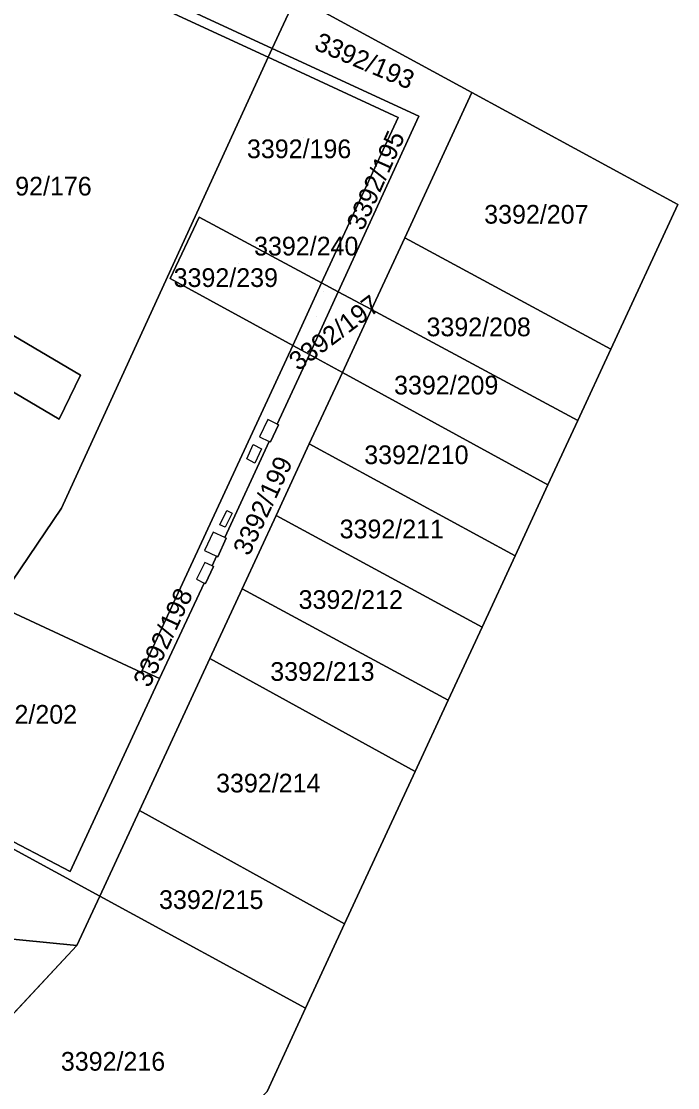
# Model space of a CAD drawing. Extents: x -262715 to -259381, y -1237238 to -1231182.
# Drawn here: x -261371.9 to -261301.7, y -1236043.8 to -1235929.8 of the extents above; entities that cross this region are included whole.
import ezdxf

# ---------------------------------------------------------------- set-up
doc = ezdxf.new("R2010")
doc.units = 0
for name, color, linetype in [('body_kn', 7, 'Continuous'), ('kladpar_druhypozemkov', 7, 'Continuous'), ('kladpar_hranice', 7, 'Continuous'), ('kladpar_parcelnecisla', 7, 'Continuous'), ('kladpar_plochy', 7, 'Continuous'), ('kladpar_sipky', 7, 'Continuous'), ('zappar_hrandruhpozemk', 7, 'Continuous'), ('zuob_linie', 7, 'Continuous'), ('zuob_plochy', 7, 'Continuous')]:
    doc.layers.add(name, color=color, linetype=linetype)

msp = doc.modelspace()

# ---------------------------------------------------------------- linework, layer by layer
at = {"layer": 'body_kn'}
for p, q in [((-261345.49, -1235933.67), (-261345.49, -1235933.67)), ((-261345.49, -1235933.67), (-261345.49, -1235933.67)), ((-261345.06, -1235932.74), (-261345.06, -1235932.74)), ((-261323.71, -1235937.45), (-261323.71, -1235937.45)), ((-261323.71, -1235937.45), (-261323.71, -1235937.45)), ((-261331.59, -1235940.11), (-261331.59, -1235940.11)), ((-261331.59, -1235940.11), (-261331.59, -1235940.11)), ((-261329.38, -1235939.99), (-261329.38, -1235939.99)), ((-261301.71, -1235949.44), (-261301.71, -1235949.44)), ((-261352.89, -1235950.78), (-261352.89, -1235950.78)), ((-261330.9, -1235952.98), (-261330.9, -1235952.98)), ((-261330.9, -1235952.98), (-261330.9, -1235952.98)), ((-261355.98, -1235957.32), (-261355.98, -1235957.32)), ((-261339.79, -1235957.8), (-261339.79, -1235957.8)), ((-261339.79, -1235957.8), (-261339.79, -1235957.8)), ((-261338.02, -1235958.75), (-261338.02, -1235958.75)), ((-261334.46, -1235960.66), (-261334.46, -1235960.66)), ((-261334.46, -1235960.66), (-261334.46, -1235960.66)), ((-261342.88, -1235964.48), (-261342.88, -1235964.48)), ((-261342.88, -1235964.48), (-261342.88, -1235964.48)), ((-261341.1, -1235965.45), (-261341.1, -1235965.45)), ((-261308.86, -1235964.89), (-261308.86, -1235964.89)), ((-261308.86, -1235964.89), (-261308.86, -1235964.89)), ((-261365.58, -1235967.67), (-261365.58, -1235967.67)), ((-261365.58, -1235967.67), (-261365.58, -1235967.67)), ((-261337.57, -1235967.38), (-261337.57, -1235967.38)), ((-261337.57, -1235967.38), (-261337.57, -1235967.38)), ((-261367.87, -1235972.36), (-261367.87, -1235972.36)), ((-261345.53, -1235972.42), (-261345.53, -1235972.42)), ((-261312.39, -1235972.5), (-261312.39, -1235972.5)), ((-261312.39, -1235972.5), (-261312.39, -1235972.5)), ((-261344.54, -1235972.92), (-261344.54, -1235972.92)), ((-261344.54, -1235972.92), (-261344.54, -1235972.92)), ((-261344.4, -1235972.99), (-261344.4, -1235972.99)), ((-261346.42, -1235974.27), (-261346.42, -1235974.27)), ((-261345.38, -1235974.75), (-261345.38, -1235974.75)), ((-261345.24, -1235974.81), (-261345.24, -1235974.81)), ((-261347.09, -1235975.08), (-261347.09, -1235975.08)), ((-261346.22, -1235975.54), (-261346.22, -1235975.54)), ((-261346.22, -1235975.54), (-261346.22, -1235975.54)), ((-261341.11, -1235975.02), (-261341.11, -1235975.02)), ((-261341.11, -1235975.02), (-261341.11, -1235975.02)), ((-261347.79, -1235976.62), (-261347.79, -1235976.62)), ((-261346.92, -1235977.06), (-261346.92, -1235977.06)), ((-261315.58, -1235979.39), (-261315.58, -1235979.39)), ((-261315.58, -1235979.39), (-261315.58, -1235979.39)), ((-261367.6, -1235981.9), (-261367.6, -1235981.9)), ((-261349.93, -1235982.14), (-261349.93, -1235982.14)), ((-261349.37, -1235982.41), (-261349.37, -1235982.41)), ((-261349.37, -1235982.41), (-261349.37, -1235982.41)), ((-261344.65, -1235982.66), (-261344.65, -1235982.66)), ((-261344.65, -1235982.66), (-261344.65, -1235982.66)), ((-261350.66, -1235983.66), (-261350.66, -1235983.66)), ((-261350.1, -1235983.93), (-261350.1, -1235983.93)), ((-261351.39, -1235984.44), (-261351.39, -1235984.44)), ((-261350.12, -1235985.03), (-261350.12, -1235985.03)), ((-261350.12, -1235985.03), (-261350.12, -1235985.03)), ((-261350, -1235985.09), (-261350, -1235985.09)), ((-261352.32, -1235986.4), (-261352.32, -1235986.4)), ((-261351.04, -1235987.03), (-261351.04, -1235987.03)), ((-261350.9, -1235987.1), (-261350.9, -1235987.1)), ((-261319.1, -1235986.99), (-261319.1, -1235986.99)), ((-261319.1, -1235986.99), (-261319.1, -1235986.99)), ((-261352.27, -1235987.68), (-261352.27, -1235987.68)), ((-261351.5, -1235988.04), (-261351.5, -1235988.04)), ((-261351.5, -1235988.04), (-261351.5, -1235988.04)), ((-261351.35, -1235988.11), (-261351.35, -1235988.11)), ((-261353.17, -1235989.48), (-261353.17, -1235989.48)), ((-261352.35, -1235989.89), (-261352.35, -1235989.89)), ((-261352.21, -1235989.96), (-261352.21, -1235989.96)), ((-261348.29, -1235990.52), (-261348.29, -1235990.52)), ((-261348.29, -1235990.52), (-261348.29, -1235990.52)), ((-261322.63, -1235994.6), (-261322.63, -1235994.6)), ((-261322.63, -1235994.6), (-261322.63, -1235994.6)), ((-261351.74, -1235997.96), (-261351.74, -1235997.96)), ((-261351.74, -1235997.96), (-261351.74, -1235997.96)), ((-261359.06, -1235999.44), (-261359.06, -1235999.44)), ((-261359.06, -1235999.44), (-261359.06, -1235999.44)), ((-261358.98, -1235999.25), (-261358.98, -1235999.25)), ((-261358.98, -1235999.25), (-261358.98, -1235999.25)), ((-261357.12, -1236000.09), (-261357.12, -1236000.09)), ((-261326.26, -1236002.43), (-261326.26, -1236002.43)), ((-261326.26, -1236002.43), (-261326.26, -1236002.43)), ((-261329.78, -1236010.04), (-261329.78, -1236010.04)), ((-261329.78, -1236010.04), (-261329.78, -1236010.04)), ((-261359.26, -1236014.2), (-261359.26, -1236014.2)), ((-261359.26, -1236014.2), (-261359.26, -1236014.2)), ((-261366.66, -1236020.74), (-261366.66, -1236020.74)), ((-261363.51, -1236023.37), (-261363.51, -1236023.37)), ((-261363.51, -1236023.37), (-261363.51, -1236023.37)), ((-261337.33, -1236026.34), (-261337.33, -1236026.34)), ((-261337.33, -1236026.34), (-261337.33, -1236026.34)), ((-261365.96, -1236028.66), (-261365.96, -1236028.66)), ((-261365.96, -1236028.66), (-261365.96, -1236028.66)), ((-261341.5, -1236035.34), (-261341.5, -1236035.34)), ((-261341.5, -1236035.34), (-261341.5, -1236035.34))]:
    msp.add_line(p, q, dxfattribs=at)
at = {"layer": 'kladpar_druhypozemkov'}
for p, q in [((-261333.62, -1235933.87), (-261333.62, -1235933.87)), ((-261341.71, -1235942.24), (-261341.71, -1235942.24)), ((-261331.15, -1235942.12), (-261331.15, -1235942.12)), ((-261369.71, -1235946.22), (-261369.71, -1235946.22)), ((-261315.71, -1235949.59), (-261315.71, -1235949.59)), ((-261348.71, -1235955.73), (-261348.71, -1235955.73)), ((-261322.04, -1235961.03), (-261322.04, -1235961.03)), ((-261340.38, -1235961.45), (-261340.38, -1235961.45)), ((-261337.55, -1235961.63), (-261337.55, -1235961.63)), ((-261326.52, -1235968.14), (-261326.52, -1235968.14)), ((-261329.49, -1235975.4), (-261329.49, -1235975.4)), ((-261346.4, -1235980.79), (-261346.4, -1235980.79)), ((-261332.46, -1235983.48), (-261332.46, -1235983.48)), ((-261353.75, -1235990.87), (-261353.75, -1235990.87)), ((-261336.31, -1235991.07), (-261336.31, -1235991.07)), ((-261339.57, -1235998.82), (-261339.57, -1235998.82)), ((-261369.87, -1236003.1), (-261369.87, -1236003.1)), ((-261344.78, -1236010.35), (-261344.78, -1236010.35)), ((-261351.16, -1236022.87), (-261351.16, -1236022.87)), ((-261361.38, -1236039.96), (-261361.38, -1236039.96))]:
    msp.add_line(p, q, dxfattribs=at)
at = {"layer": 'kladpar_hranice'}
for p, q in [((-261330.9, -1235952.98), (-261323.71, -1235937.45)), ((-261339.79, -1235957.8), (-261331.59, -1235940.11)), ((-261342.88, -1235964.48), (-261339.79, -1235957.8)), ((-261339.79, -1235957.8), (-261342.88, -1235964.48)), ((-261338.02, -1235958.75), (-261341.1, -1235965.45)), ((-261341.1, -1235965.45), (-261338.02, -1235958.75)), ((-261339.79, -1235957.8), (-261338.02, -1235958.75)), ((-261338.02, -1235958.75), (-261339.79, -1235957.8)), ((-261338.02, -1235958.75), (-261334.46, -1235960.66)), ((-261358.98, -1235999.25), (-261342.88, -1235964.48)), ((-261341.1, -1235965.45), (-261342.88, -1235964.48)), ((-261342.88, -1235964.48), (-261341.1, -1235965.45)), ((-261383.94, -1236047.9), (-261365.96, -1236028.66))]:
    msp.add_line(p, q, dxfattribs=at)
for points in [[(-261386.5, -1236069.65), (-261377.1, -1236074.79), (-261372.8, -1236072.22), (-261361.27, -1236060.35), (-261345.62, -1236044.25), (-261341.5, -1236035.34), (-261337.33, -1236026.34), (-261329.78, -1236010.04), (-261326.26, -1236002.43), (-261322.63, -1235994.6), (-261319.1, -1235986.99), (-261315.58, -1235979.39), (-261312.39, -1235972.5), (-261308.86, -1235964.89), (-261301.71, -1235949.44), (-261323.71, -1235937.45), (-261341.89, -1235927.54), (-261342.66, -1235927.5), (-261305.98, -1235847.48)], [(-261342.66, -1235927.5), (-261345.06, -1235932.74), (-261371.51, -1235920.48), (-261371.49, -1235920.03), (-261371.41, -1235919.44), (-261371.21, -1235918.88), (-261369.08, -1235914.38), (-261379.31, -1235909.59)], [(-261345.49, -1235933.67), (-261370.16, -1235922.25), (-261370.19, -1235922.32), (-261370.81, -1235921.97), (-261371.03, -1235921.8), (-261371.22, -1235921.56), (-261371.45, -1235921.01), (-261371.51, -1235920.48), (-261345.06, -1235932.74), (-261345.49, -1235933.67)], [(-261385.72, -1235955.84), (-261372.29, -1235926.85), (-261370.19, -1235922.32), (-261370.16, -1235922.25), (-261345.49, -1235933.67), (-261367.6, -1235981.9), (-261374.62, -1235992.24), (-261397.64, -1235981.58), (-261397.56, -1235981.41), (-261396.6, -1235979.34), (-261394.51, -1235974.82)], [(-261338.02, -1235958.75), (-261329.38, -1235939.99), (-261345.06, -1235932.74), (-261342.66, -1235927.5)], [(-261341.89, -1235927.54), (-261323.71, -1235937.45), (-261330.9, -1235952.98), (-261334.46, -1235960.66), (-261338.02, -1235958.75)], [(-261342.88, -1235964.48), (-261358.98, -1235999.25), (-261359.06, -1235999.44), (-261374.62, -1235992.24), (-261367.6, -1235981.9), (-261345.49, -1235933.67)], [(-261331.59, -1235940.11), (-261345.49, -1235933.67), (-261345.06, -1235932.74), (-261329.38, -1235939.99), (-261338.02, -1235958.75)], [(-261345.49, -1235933.67), (-261331.59, -1235940.11), (-261339.79, -1235957.8)], [(-261323.71, -1235937.45), (-261301.71, -1235949.44), (-261308.86, -1235964.89), (-261330.9, -1235952.98)], [(-261342.88, -1235964.48), (-261355.98, -1235957.32), (-261352.89, -1235950.78), (-261339.79, -1235957.8)], [(-261339.79, -1235957.8), (-261352.89, -1235950.78), (-261355.98, -1235957.32), (-261342.88, -1235964.48)], [(-261334.46, -1235960.66), (-261330.9, -1235952.98), (-261308.86, -1235964.89)], [(-261365.58, -1235967.67), (-261381.27, -1235958.45), (-261385.72, -1235955.84)], [(-261385.72, -1235955.84), (-261381.27, -1235958.45), (-261365.58, -1235967.67)], [(-261387.89, -1235960.55), (-261384.17, -1235962.74), (-261367.87, -1235972.36), (-261365.58, -1235967.67)], [(-261365.58, -1235967.67), (-261367.87, -1235972.36), (-261384.17, -1235962.74), (-261387.89, -1235960.55)], [(-261334.46, -1235960.66), (-261337.57, -1235967.38), (-261341.1, -1235965.45)], [(-261337.57, -1235967.38), (-261334.46, -1235960.66), (-261312.39, -1235972.5)], [(-261308.86, -1235964.89), (-261312.39, -1235972.5), (-261334.46, -1235960.66)], [(-261390.31, -1236026.25), (-261389.52, -1236024.31), (-261383.32, -1236012.04), (-261366.66, -1236020.74), (-261357.12, -1236000.09), (-261352.35, -1235989.89), (-261352.21, -1235989.96), (-261351.35, -1235988.11), (-261351.5, -1235988.04), (-261351.04, -1235987.03), (-261350.9, -1235987.1), (-261350, -1235985.09), (-261350.12, -1235985.03), (-261345.38, -1235974.75), (-261345.24, -1235974.81), (-261344.4, -1235972.99), (-261344.54, -1235972.92), (-261341.1, -1235965.45)], [(-261341.1, -1235965.45), (-261337.57, -1235967.38), (-261341.11, -1235975.02), (-261344.65, -1235982.66), (-261348.29, -1235990.52), (-261351.74, -1235997.96), (-261359.26, -1236014.2), (-261363.51, -1236023.37), (-261383.03, -1236012.76)], [(-261341.1, -1235965.45), (-261344.54, -1235972.92), (-261344.4, -1235972.99), (-261345.24, -1235974.81), (-261345.38, -1235974.75), (-261350.12, -1235985.03), (-261350, -1235985.09), (-261350.9, -1235987.1), (-261351.04, -1235987.03), (-261351.5, -1235988.04), (-261351.35, -1235988.11), (-261352.21, -1235989.96), (-261352.35, -1235989.89), (-261357.12, -1236000.09), (-261358.98, -1235999.25)], [(-261341.11, -1235975.02), (-261337.57, -1235967.38), (-261315.58, -1235979.39)], [(-261312.39, -1235972.5), (-261315.58, -1235979.39), (-261337.57, -1235967.38)], [(-261344.65, -1235982.66), (-261341.11, -1235975.02), (-261319.1, -1235986.99)], [(-261315.58, -1235979.39), (-261319.1, -1235986.99), (-261341.11, -1235975.02)], [(-261348.29, -1235990.52), (-261344.65, -1235982.66), (-261322.63, -1235994.6)], [(-261319.1, -1235986.99), (-261322.63, -1235994.6), (-261344.65, -1235982.66)], [(-261351.74, -1235997.96), (-261348.29, -1235990.52), (-261326.26, -1236002.43)], [(-261322.63, -1235994.6), (-261326.26, -1236002.43), (-261348.29, -1235990.52)], [(-261359.06, -1235999.44), (-261358.98, -1235999.25), (-261357.12, -1236000.09), (-261366.66, -1236020.74), (-261383.32, -1236012.04), (-261389.52, -1236024.31), (-261379.2, -1235999), (-261374.62, -1235992.24), (-261359.06, -1235999.44)], [(-261359.26, -1236014.2), (-261351.74, -1235997.96), (-261329.78, -1236010.04)], [(-261326.26, -1236002.43), (-261329.78, -1236010.04), (-261351.74, -1235997.96)], [(-261329.78, -1236010.04), (-261337.33, -1236026.34), (-261359.26, -1236014.2)], [(-261383.03, -1236012.76), (-261363.51, -1236023.37), (-261365.96, -1236028.66), (-261389.8, -1236026.3)], [(-261363.51, -1236023.37), (-261359.26, -1236014.2), (-261337.33, -1236026.34)], [(-261365.96, -1236028.66), (-261363.51, -1236023.37), (-261341.5, -1236035.34)], [(-261337.33, -1236026.34), (-261341.5, -1236035.34), (-261363.51, -1236023.37)], [(-261390.31, -1236026.25), (-261389.8, -1236026.3), (-261365.96, -1236028.66), (-261383.94, -1236047.9)], [(-261341.5, -1236035.34), (-261345.62, -1236044.25), (-261361.27, -1236060.35), (-261377.4, -1236051.49)]]:
    msp.add_lwpolyline(points, dxfattribs=at)
at = {"layer": 'kladpar_plochy'}
for points in [[(-261345.62, -1236044.25), (-261341.5, -1236035.34), (-261337.33, -1236026.34), (-261329.78, -1236010.04), (-261326.26, -1236002.43), (-261322.63, -1235994.6), (-261319.1, -1235986.99), (-261315.58, -1235979.39), (-261312.39, -1235972.5), (-261308.86, -1235964.89), (-261301.71, -1235949.44), (-261323.71, -1235937.45), (-261341.89, -1235927.54), (-261342.66, -1235927.5), (-261305.98, -1235847.48)], [(-261383.32, -1236012.04), (-261366.66, -1236020.74), (-261357.12, -1236000.09), (-261352.35, -1235989.89), (-261352.21, -1235989.96), (-261351.35, -1235988.11), (-261351.5, -1235988.04), (-261351.04, -1235987.03), (-261350.9, -1235987.1), (-261350, -1235985.09), (-261350.12, -1235985.03), (-261345.38, -1235974.75), (-261345.24, -1235974.81), (-261344.4, -1235972.99), (-261344.54, -1235972.92), (-261341.1, -1235965.45), (-261337.57, -1235967.38), (-261341.11, -1235975.02), (-261344.65, -1235982.66), (-261348.29, -1235990.52), (-261351.74, -1235997.96), (-261359.26, -1236014.2), (-261363.51, -1236023.37), (-261383.03, -1236012.76)]]:
    msp.add_lwpolyline(points, dxfattribs=at)
for points in [[(-261356.13, -1235921.41), (-261346.13, -1235927.3), (-261342.66, -1235927.5), (-261345.06, -1235932.74), (-261371.51, -1235920.48), (-261371.49, -1235920.03), (-261371.41, -1235919.44), (-261371.21, -1235918.88), (-261369.08, -1235914.38), (-261379.31, -1235909.59), (-261378.64, -1235908.15)], [(-261345.49, -1235933.67), (-261370.16, -1235922.25), (-261370.19, -1235922.32), (-261370.81, -1235921.97), (-261371.03, -1235921.8), (-261371.22, -1235921.56), (-261371.45, -1235921.01), (-261371.51, -1235920.48), (-261345.06, -1235932.74)], [(-261365.58, -1235967.67), (-261381.27, -1235958.45), (-261385.72, -1235955.84), (-261372.29, -1235926.85), (-261370.19, -1235922.32), (-261370.16, -1235922.25), (-261345.49, -1235933.67), (-261367.6, -1235981.9), (-261374.62, -1235992.24), (-261397.64, -1235981.58), (-261397.56, -1235981.41), (-261396.6, -1235979.34), (-261394.51, -1235974.82), (-261392.97, -1235975.72), (-261374.7, -1235986.37), (-261373.56, -1235984.04), (-261391.5, -1235973.55), (-261393.4, -1235972.44), (-261387.89, -1235960.55), (-261384.17, -1235962.74), (-261367.87, -1235972.36)], [(-261341.89, -1235927.54), (-261323.71, -1235937.45), (-261330.9, -1235952.98), (-261334.46, -1235960.66), (-261338.02, -1235958.75), (-261329.38, -1235939.99), (-261345.06, -1235932.74), (-261342.66, -1235927.5)], [(-261345.49, -1235933.67), (-261331.59, -1235940.11), (-261339.79, -1235957.8), (-261352.89, -1235950.78), (-261355.98, -1235957.32), (-261342.88, -1235964.48), (-261358.98, -1235999.25), (-261359.06, -1235999.44), (-261374.62, -1235992.24), (-261367.6, -1235981.9)], [(-261331.59, -1235940.11), (-261345.49, -1235933.67), (-261345.06, -1235932.74), (-261329.38, -1235939.99), (-261338.02, -1235958.75), (-261339.79, -1235957.8)], [(-261323.71, -1235937.45), (-261301.71, -1235949.44), (-261308.86, -1235964.89), (-261330.9, -1235952.98)], [(-261339.79, -1235957.8), (-261342.88, -1235964.48), (-261355.98, -1235957.32), (-261352.89, -1235950.78)], [(-261334.46, -1235960.66), (-261330.9, -1235952.98), (-261308.86, -1235964.89), (-261312.39, -1235972.5)], [(-261365.58, -1235967.67), (-261367.87, -1235972.36), (-261384.17, -1235962.74), (-261387.89, -1235960.55), (-261385.72, -1235955.84), (-261381.27, -1235958.45)], [(-261342.88, -1235964.48), (-261339.79, -1235957.8), (-261338.02, -1235958.75), (-261341.1, -1235965.45)], [(-261334.46, -1235960.66), (-261337.57, -1235967.38), (-261341.1, -1235965.45), (-261338.02, -1235958.75)], [(-261337.57, -1235967.38), (-261334.46, -1235960.66), (-261312.39, -1235972.5), (-261315.58, -1235979.39)], [(-261358.98, -1235999.25), (-261342.88, -1235964.48), (-261341.1, -1235965.45), (-261344.54, -1235972.92), (-261344.4, -1235972.99), (-261345.24, -1235974.81), (-261345.38, -1235974.75), (-261350.12, -1235985.03), (-261350, -1235985.09), (-261350.9, -1235987.1), (-261351.04, -1235987.03), (-261351.5, -1235988.04), (-261351.35, -1235988.11), (-261352.21, -1235989.96), (-261352.35, -1235989.89), (-261357.12, -1236000.09)], [(-261341.11, -1235975.02), (-261337.57, -1235967.38), (-261315.58, -1235979.39), (-261319.1, -1235986.99)], [(-261344.65, -1235982.66), (-261341.11, -1235975.02), (-261319.1, -1235986.99), (-261322.63, -1235994.6)], [(-261348.29, -1235990.52), (-261344.65, -1235982.66), (-261322.63, -1235994.6), (-261326.26, -1236002.43)], [(-261351.74, -1235997.96), (-261348.29, -1235990.52), (-261326.26, -1236002.43), (-261329.78, -1236010.04)], [(-261359.06, -1235999.44), (-261358.98, -1235999.25), (-261357.12, -1236000.09), (-261366.66, -1236020.74), (-261383.32, -1236012.04), (-261389.52, -1236024.31), (-261379.2, -1235999), (-261374.62, -1235992.24)], [(-261359.26, -1236014.2), (-261351.74, -1235997.96), (-261329.78, -1236010.04), (-261337.33, -1236026.34)], [(-261383.03, -1236012.76), (-261363.51, -1236023.37), (-261365.96, -1236028.66), (-261389.8, -1236026.3)], [(-261363.51, -1236023.37), (-261359.26, -1236014.2), (-261337.33, -1236026.34), (-261341.5, -1236035.34)], [(-261365.96, -1236028.66), (-261363.51, -1236023.37), (-261341.5, -1236035.34), (-261345.62, -1236044.25), (-261361.27, -1236060.35), (-261377.4, -1236051.49), (-261383.94, -1236047.9)], [(-261390.31, -1236026.25), (-261389.8, -1236026.3), (-261365.96, -1236028.66), (-261383.94, -1236047.9), (-261396.36, -1236041.07), (-261392.68, -1236032.07)]]:
    msp.add_lwpolyline(points, close=True, dxfattribs=at)
at = {"layer": 'kladpar_sipky'}
msp.add_line((-261339.6, -1235958.76), (-261339.6, -1235958.76), dxfattribs=at)
at = {"layer": 'zappar_hrandruhpozemk'}
for p, q in [((-261345.53, -1235972.42), (-261346.42, -1235974.27)), ((-261344.54, -1235972.92), (-261345.53, -1235972.42)), ((-261346.42, -1235974.27), (-261345.38, -1235974.75)), ((-261347.79, -1235976.62), (-261347.09, -1235975.08)), ((-261347.09, -1235975.08), (-261346.22, -1235975.54)), ((-261350.66, -1235983.66), (-261349.93, -1235982.14)), ((-261349.93, -1235982.14), (-261349.37, -1235982.41)), ((-261351.39, -1235984.44), (-261352.32, -1235986.4)), ((-261350.12, -1235985.03), (-261351.39, -1235984.44)), ((-261352.32, -1235986.4), (-261351.04, -1235987.03)), ((-261352.27, -1235987.68), (-261353.17, -1235989.48)), ((-261351.5, -1235988.04), (-261352.27, -1235987.68)), ((-261353.17, -1235989.48), (-261352.35, -1235989.89))]:
    msp.add_line(p, q, dxfattribs=at)
for points in [[(-261346.22, -1235975.54), (-261346.92, -1235977.06), (-261347.79, -1235976.62)], [(-261349.37, -1235982.41), (-261350.1, -1235983.93), (-261350.66, -1235983.66)]]:
    msp.add_lwpolyline(points, dxfattribs=at)
at = {"layer": 'zuob_linie'}
for points in [[(-261400, -1236050), (-261396.36, -1236041.07), (-261392.68, -1236032.07), (-261390.31, -1236026.25), (-261389.52, -1236024.31), (-261379.2, -1235999), (-261374.62, -1235992.24), (-261367.6, -1235981.9), (-261345.49, -1235933.67), (-261345.06, -1235932.74), (-261342.66, -1235927.5), (-261305.98, -1235847.48)], [(-261305.98, -1235847.48), (-261342.66, -1235927.5), (-261345.06, -1235932.74), (-261345.49, -1235933.67), (-261367.6, -1235981.9), (-261374.62, -1235992.24), (-261379.2, -1235999), (-261389.52, -1236024.31), (-261390.31, -1236026.25), (-261392.68, -1236032.07), (-261396.36, -1236041.07), (-261400, -1236050)]]:
    msp.add_lwpolyline(points, dxfattribs=at)
at = {"layer": 'zuob_plochy'}
for points in [[(-261400, -1236050), (-261396.36, -1236041.07), (-261392.68, -1236032.07), (-261390.31, -1236026.25), (-261389.52, -1236024.31), (-261379.2, -1235999), (-261374.62, -1235992.24), (-261367.6, -1235981.9), (-261345.49, -1235933.67), (-261345.06, -1235932.74), (-261342.66, -1235927.5), (-261305.98, -1235847.48)], [(-261305.98, -1235847.48), (-261342.66, -1235927.5), (-261345.06, -1235932.74), (-261345.49, -1235933.67), (-261367.6, -1235981.9), (-261374.62, -1235992.24), (-261379.2, -1235999), (-261389.52, -1236024.31), (-261390.31, -1236026.25), (-261392.68, -1236032.07), (-261396.36, -1236041.07), (-261400, -1236050)]]:
    msp.add_lwpolyline(points, dxfattribs=at)

# ---------------------------------------------------------------- texts
at = {"layer": 'kladpar_parcelnecisla'}
for s, rotation, p in [('3392/193', 337, (-261340.7, -1235932.8)), ('3392/195', 66, (-261335.37, -1235952.33)), ('3392/197', 37, (-261342.3, -1235967.28)), ('3392/199', 65, (-261347.54, -1235987.09)), ('3392/198', 65, (-261358.21, -1236001.18))]:
    msp.add_text(s, height=2, rotation=rotation, dxfattribs=at).set_placement(p)
for s, p in [('3392/196', (-261347.77, -1235944.47)), ('3392/176', (-261375.53, -1235948.46)), ('3392/207', (-261322.4, -1235951.47)), ('3392/240', (-261347.01, -1235954.87)), ('3392/239', (-261355.61, -1235958.24)), ('3392/208', (-261328.57, -1235963.51)), ('3392/209', (-261332.04, -1235969.73)), ('3392/210', (-261335.23, -1235977.18)), ('3392/211', (-261337.86, -1235985.11)), ('3392/212', (-261342.25, -1235992.66)), ('3392/213', (-261345.28, -1236000.35)), ('3392/202', (-261377.09, -1236004.93)), ('3392/214', (-261351.07, -1236012.28)), ('3392/215', (-261357.17, -1236024.74)), ('3392/216', (-261367.67, -1236042.03))]:
    msp.add_text(s, height=2, dxfattribs=at).set_placement(p)

doc.saveas('drawing.dxf')
